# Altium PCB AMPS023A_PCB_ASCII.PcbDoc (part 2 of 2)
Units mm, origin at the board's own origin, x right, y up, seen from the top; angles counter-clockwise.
Board outline 85 x 120 mm, 4 copper layers (Top Layer, Signal Layer 1, Signal Layer 2, Bottom Layer), stack 1.567 mm thick; 131 components, 63 nets, 410 pads, 509 vias.
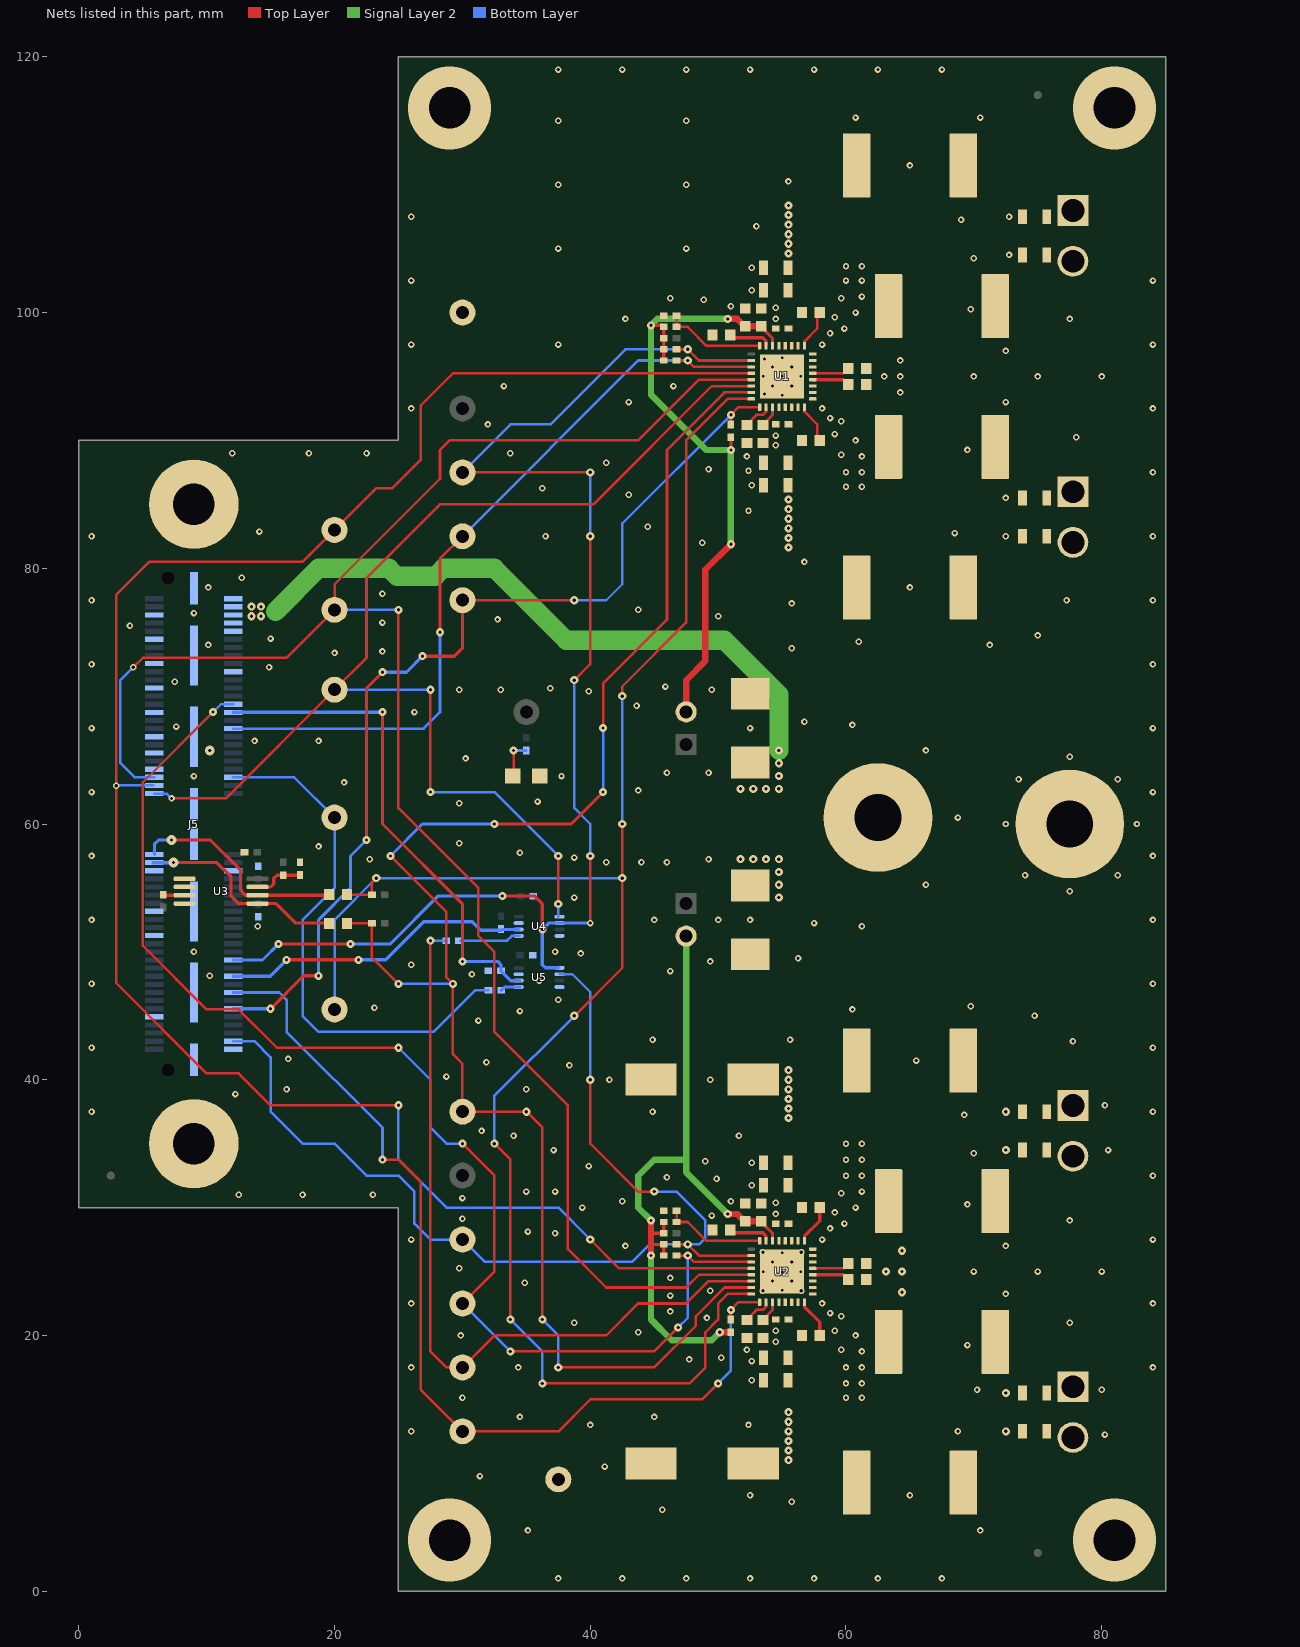
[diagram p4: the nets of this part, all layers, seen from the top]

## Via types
v1: diameter 0.508, hole 0.254, Top Layer to Bottom Layer, tented both sides, 343 vias
v2: diameter 0.635, hole 0.254, Top Layer to Bottom Layer, tented both sides, 130 vias
v3: diameter 0.508, hole 0.254, Top Layer to Bottom Layer, 14 vias
v4: diameter 0.5, hole 0.2, Top Layer to Bottom Layer, 10 vias
v5: diameter 0.762, hole 0.254, Top Layer to Bottom Layer, tented both sides, 8 vias
v6: diameter 6.5, hole 3.25, Top Layer to Bottom Layer, tented both sides, 4 vias

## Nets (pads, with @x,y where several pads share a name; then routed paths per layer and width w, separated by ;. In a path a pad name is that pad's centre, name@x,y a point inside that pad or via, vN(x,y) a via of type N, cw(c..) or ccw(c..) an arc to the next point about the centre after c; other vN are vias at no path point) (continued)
\MUTE1: J5.78 R21.1 TP14.1 U1.10 U4.2 U5.1 | length 110.7
  Top Layer w0.2: TP14.1@30,87.5 v2(40,87.5) ; v2(38.75,71.25) 40,72.5 v2(40,82.5) ; v2(40,57.5) 40,52.253 v1(40.005,52.248) ; R21.1@46.75,97.125 v2(47.625,97.125) 48.5,96.25 U1.10@52.6,96.25
  Top Layer w0.25: v2(15.625,50.625) v2(21.25,50.625) ; v2(33.125,54.375) 35.625,54.375 36.25,53.75 v2(36.25,51.744)
  Bottom Layer w0.2: TP14.1@30,87.5 33.75,91.25 36.875,91.25 42.75,97.125 v2(47.625,97.125) ; v2(38.75,71.25) 38.75,61.25 40,60 v2(40,57.5) ; v2(40,82.5) v2(40,87.5)
  Bottom Layer w0.25: J5.78@12.086,49.364 14.364,49.364 v2(15.625,50.625) ; v2(21.25,50.625) 24.375,50.625 28.125,54.375 v2(33.125,54.375)
  Bottom Layer w0.254: U5.1@37.5,48.75 36.5,48.75 36.25,49 v2(36.25,51.744) 36.756,52.25 40.003,52.25 v1(40.005,52.248)
\MUTE2: J5.98 R4.1 TP15.1 U2.10 U5.2 | length 82.7
  Top Layer w0.2: v2(40,40) 40,35 43.75,31.25 v2(45,31.25) ; R4.1@46.75,27.125 v2(47.625,27.125) 48.5,26.25 U2.10@52.6,26.25
  Bottom Layer w0.2: J5.98@12.086,43.014 13.736,43.014 15,41.75 15,37.5 17.5,35 20,35 22.5,32.5 25,32.5 26.25,31.25 26.25,28.75 27.5,27.5 TP15.1@30,27.5 31.75,25.75 43.25,25.75 44.625,27.125 v2(47.625,27.125) 48.5,27.125 49,27.625 49,29 46.75,31.25 v2(45,31.25) ; U5.2@37.6,48.25 38.6,48.25 40,46.85 v2(40,40)
\PDN1: J5.90 R23.1 TP18.1 U1.17 | length 77.4
  Top Layer w0.2: TP18.1@30,77.5 v2(38.75,77.5) ; R23.1@51,91.25 v2(51,92) 51.6,92.6 U1.17@53.25,92.6
  Top Layer w0.25: v2(15,45.554) 17.571,48.125 v2(18.75,48.125) ; v2(22.5,58.75) 22.5,70.625 v2(23.75,71.875) ; v2(26.875,73.125) 29.375,73.125 30,73.75 TP18.1@30,77.5
  Bottom Layer w0.2: J5.90@12.086,45.554 J5.90@12.086,45.57 ; v2(38.75,77.5) 41.25,77.5 42.5,78.75 42.5,83.5 v2(51,92)
  Bottom Layer w0.25: J5.90@12.086,45.554 v2(15,45.554) ; v2(18.75,48.125) 18.75,52.5 21.25,55 21.25,57.5 v2(22.5,58.75) ; v2(23.75,71.875) 25.625,71.875 v2(26.875,73.125)
\PDN2: J5.86 R6.1 TP17.1 U2.17 | length 75.5
  Top Layer w0.2: v2(23.75,33.75) 25,33.75 26.75,32 26.75,15.75 TP17.1@30,12.5 37.5,12.5 40,15 48.75,15 v2(50,16.25) ; R6.1@51,21.25 v2(51,22) 51.6,22.6 U2.17@53.25,22.6
  Bottom Layer w0.2: J5.86@12.086,46.824 15.676,46.824 16.25,46.25 16.25,43.75 23.75,36.25 v2(23.75,33.75) ; v2(50,16.25) 51,17.25 v2(51,22)
\WARN1: J5.34 R22.1 TP8.1 U1.11 | length 60.6
  Top Layer w0.2: v2(28.25,75) 28.25,80.75 TP8.1@30,82.5 ; R22.1@46.75,96.25 v2(47.625,96.25) 48.125,95.75 U1.11@52.6,95.75
  Bottom Layer w0.2: J5.34@12.086,67.461 26.961,67.461 28.25,68.75 v2(28.25,75) ; TP8.1@30,82.5 43.75,96.25 v2(47.625,96.25)
\WARN2: J5.28 R5.1 TP9.1 U2.11 | length 101.8
  Top Layer w0.2: v2(10.5,68.75) 5,63.25 5,50.5 10,45.5 12.5,45.5 15.5,42.5 v2(25,42.5) ; TP9.1@30,22.5 32.5,25 32.5,32.5 v2(30,35) ; v2(33.75,18.75) 45,18.75 v2(46.875,20.625) ; R5.1@46.75,26.25 v2(47.625,26.25) 48.125,25.75 U2.11@52.6,25.75
  Bottom Layer w0.2: v2(10.5,68.75) 11.116,69.366 J5.28@12.086,69.366 ; v2(25,42.5) 27.5,40 27.5,36.25 28.75,35 v2(30,35) ; TP9.1@30,22.5 v2(33.75,18.75) ; v2(46.875,20.625) 47.625,21.375 v2(47.625,26.25)
ADR1: R1.1 R17.1 U1.8 | length 8
  Top Layer w0.2: R1.1@46.75,99.75 R17.1@46.75,98.875 47.625,98.875 49.1,97.4 U1.8@53.25,97.4
ADR2: R2.1 R24.1 U2.8 | length 8
  Top Layer w0.2: R2.1@46.75,29.75 R24.1@46.75,28.875 47.625,28.875 49.1,27.4 U2.8@53.25,27.4
BST_A1+: C6.1 U1.1 | length 3.1
  Top Layer w0.2: U1.1@56.75,97.4 56.75,97.75 57.75,98.75 57.75,99.8 C6.1@57.95,100
BST_A1-: C9.1 U1.29 | length 3
  Top Layer w0.2: U1.29@57.4,95.25 59.8,95.25 C9.1@60.175,95.625 ; C9.1@60.237,95.562 C9.1@60.3,95.625
BST_A2+: C24.1 U2.1 | length 3.1
  Top Layer w0.25: U2.1@56.75,27.4 56.75,27.75 57.95,28.95 C24.1@57.95,30
BST_A2-: C27.1 U2.29 | length 3
  Top Layer w0.2: U2.29@57.4,25.25 59.8,25.25 C27.1@60.175,25.625 ; C27.1@60.237,25.562 C27.1@60.3,25.625
BST_B1+: C13.1 U1.24 | length 3.1
  Top Layer w0.2: U1.24@56.75,92.6 56.75,92.25 57.75,91.25 57.75,90.2 C13.1@57.95,90
BST_B1-: C10.1 U1.28 | length 3
  Top Layer w0.25: U1.28@57.4,94.75 59.8,94.75 C10.1@60.175,94.375 ; C10.1@60.237,94.438 C10.1@60.3,94.375
BST_B2+: C30.1 U2.24 | length 3.1
  Top Layer w0.25: U2.24@56.75,22.6 56.75,22.25 57.95,21.05 C30.1@57.95,20
BST_B2-: C28.1 U2.28 | length 2.9
  Top Layer w0.25: U2.28@57.4,24.75 59.8,24.75 C28.1@60.175,24.375
DVDD1: C3.2 C4.1 J2.2 R17.2 R20.2 R21.2 R22.2 R23.2 U1.6 | length 51
  Top Layer w0.25: v2(44.75,99) 45.625,99 R17.2@45.75,98.875 R20.2@45.75,98 R21.2@45.75,97.125 R22.2@45.75,96.25 ; v2(51,89.25) R23.2@51,90.25 ; C4.1@53.375,98.865 54.25,97.99 U1.6@54.25,97.4
  Top Layer w0.5: J2.2@47.5,68.77 47.5,71.25 49,72.75 49,79.875 v2(51,81.875) ; v2(50.75,99.5) 51.489,99.5 52.064,98.925 C3.2@52.125,98.925 53.315,98.925 C4.1@53.375,98.865
  Signal Layer 2 w0.5: v2(50.75,99.5) 45.25,99.5 v2(44.75,99) 44.75,93.567 49.067,89.25 v2(51,89.25) v2(51,81.875)
DVDD2: C21.2 C22.1 J3.2 R3.2 R4.2 R5.2 R6.2 R24.2 U2.6 | length 54.7
  Top Layer w0.25: 44.75,27.125 R4.2@45.75,27.125 R5.2@45.75,26.25 ; 44.75,28 R3.2@45.75,28 R24.2@45.75,28.875 ; C22.1@53.375,28.865 54.25,27.99 U2.6@54.25,27.4
  Top Layer w0.5: v2(44.75,26.25) 44.75,27.125 44.75,28 v2(44.75,29) ; v2(50.125,20.25) R6.2@51,20.25 ; v2(50.75,29.5) 51.489,29.5 52.064,28.925 C21.2@52.125,28.925 53.315,28.925 C22.1@53.375,28.865
  Signal Layer 2 w0.5: v2(44.75,26.25) 44.75,21.25 46.375,19.625 49.5,19.625 v2(50.125,20.25) ; v2(44.75,29) 43.75,30 43.75,32.5 45,33.75 47.5,33.75 ; J3.2@47.5,51.23 47.5,33.75 ; v2(50.75,29.5) 47.5,32.75 47.5,33.75
GND: C1.2 C2.1 C3.1 C4.2 C5.2 C7.2 C8.1 C11.1 C12.1 C14.2 C15.2 C16.2 C17.1 C18.2 C19.2 C20.1 C21.1 C22.2 C23.2 C25.2 C26.2 C29.2 C31.2 C32.2 C33.2 C34.2 C35.2 C36.1 C37.1 C38.1 C39.1 C40.1 C41.2 C42.2 C43.2 C44.2 C45.1 D1.2 J5.5 J5.10 J5.11 J5.17 J5.20 J5.23 J5.29 J5.35 J5.39 J5.43 J5.55 J5.56 J5.65 J5.71 J5.91 J5.100 J5.101 J5.102 J5.103 J5.104 J5.105 J5.106 J5.107 J5.108 J7.1 pad.0 R1.2 R2.2 R10.1 R16.2 TP2.1 TP3.1 U1.5 U1.20 U1.25 U1.26 U1.31 U1.32 U1.33 U2.5 U2.20 U2.25 U2.26 U2.31 U2.32 U2.33 U3.1 U3.2 U3.4 U4.4 U4.7 U5.4 U5.7
  other v1: 37.5,1 42.5,1 47.5,1 52.5,1 57.5,1 62.5,1 67.5,1 35.125,4.75 70.5,4.75 45.625,6.375 55.75,7 52.5,7.5 65,7.5 31.375,9 41.125,9.75 80.25,12.25 26,12.5 68.75,12.5 40,13 52.375,13 34.5,13.625 45,13.625 30,15.125 60,15.125 61.25,15.125 70.25,15.75 80,15.75 60,16.25 61.25,16.25 52.625,16.5 26,17.5 34.375,17.5 60,17.5 61.25,17.5 84,17.5 52.625,18 47.75,18.125 50.25,18.25 61.25,18.75 52.25,18.875 59.625,18.875 69.5,19.25 54.5,19.5 29.875,20 60.75,20 43.75,20.25 54.5,20.375 59.125,20.375 38.75,21 77.5,21 49.125,21.375 59.625,21.5 58.75,21.75 46.25,21.875 26,22.5 58.125,22.5 84,22.5 46.25,23.125 72.5,23.25 49.375,23.5 34.875,24.125 46.25,24.5 70,25 75,25 80,25 29.75,25.25 42.75,27 72.5,27 26,27.5 58.125,27.5 84,27.5 37.25,28 35.125,28.125 58.75,28.375 59.875,28.75 77.5,29 30,29.125 49.5,29.375 54.5,29.5 59.125,29.625 39.375,30 60.75,30 69.5,30.25 54.5,30.375 42.5,30.5 51,30.5 30,30.75 12.5,31 17.5,31 23,31 59.625,31.125 35,31.25 37.25,31.25 61.25,31.25 52.625,31.75 49.875,32.25 46,32.375 60,32.5 61.25,32.5 84,32.5 39.875,33.25 52.625,33.5 49,33.625 60,33.75 61.25,33.75 70,34.25 37.125,34.5 80.5,34.5 60,35 61.25,35 34,35.625 51.625,35.625 31.5,36 69.25,37.25 1,37.5 44.875,37.5 84,37.5 80.25,38 12.25,38.875 16.25,39.25 35,39.25 41.5,40 49.375,40 28.75,40.25 38.375,41.125 31.875,41.375 65.5,41.5 16.375,41.625 1,42.5 84,42.5 77.75,43 44.875,43.125 55.625,43.125 31.25,44.625 74.75,45 34.5,45.375 60.5,45.5 23.125,45.625 69.75,45.75 37.5,46.25 1,47.5 84,47.5 36,47.75 10.25,48.125 30.75,48.25 46.25,48.5 26,49 49.375,49.25 56.25,49.5 39.25,49.875 9,50 37.25,50 14,52 61.25,52 57.5,52.25 1,52.5 45,52.5 50,52.5 52.5,52.5 84,52.5 38.75,54.25 77.5,54.75 66.25,55.25 74,56 81.25,56 41.25,57 44,57 46,57 22.75,57.25 49.25,57.25 38.75,57.375 1,57.5 84,57.5 34.5,57.75 18.75,58.25 29.75,58.5 72.5,60 82.75,60 68.75,60.5 29.75,61.625 35.875,61.75 1,62.5 84,62.5 43.75,62.625 20.75,63.25 73.5,63.5 81.25,63.5 9,63.75 37.75,63.75 46,64 49.25,64 30.25,65.125 77.5,65.25 66.25,65.75 13.75,66.5 18.75,66.5 1,67.5 52.5,67.5 84,67.5 7.625,67.625 60.5,67.75 56.75,68 26.25,68.75 43.625,69.25 39.875,70.375 29.75,70.5 33,70.5 49.5,70.5 36.875,70.625 45.875,70.75 7.5,71.125 14.875,72.25 1,72.5 84,72.5 20,73.375 23.75,73.5 55.75,73.75 10.125,74 71.25,74 61,74.25 15,74.5 75,74.75 4,75.5 23.75,75.75 32.75,76 50,76.25 9,76.5 43.75,76.75 55.75,77.25 1,77.5 77.25,77.5 84,77.5 23.75,78 10.125,78.5 65,78.5 12.75,79.25 56.75,80.5 48.75,82 1,82.5 36.5,82.5 72.5,82.5 84,82.5 68.5,82.75 14.125,82.875 44.5,83.25 52.375,84.5 72.5,85.5 43,85.75 36.25,86.25 60,86.375 61.25,86.375 52.625,86.5 60,87.5 61.25,87.5 84,87.5 52.375,87.625 49.25,87.75 41.25,88.25 52.25,88.75 61.25,88.75 59.625,88.875 12,89 18,89 22.5,89 33.75,89 69.5,89.25 54.5,89.625 60.75,90 78,90.25 54.5,90.375 59.125,90.5 32,91.25 59.625,91.5 58.75,91.75 26,92.5 58.125,92.5 84,92.5 43,93 72.5,93 64.25,93.75 33.25,94.25 46.5,94.25 63,95 64.25,95 70,95 75,95 80,95 64.25,96.25 72.5,97 26,97.5 37.5,97.5 58.125,97.5 84,97.5 58.75,98.375 59.875,98.75 42.75,99.5 54.5,99.5 77.5,99.5 59.125,99.625 60.75,100 69.75,100.25 54.5,100.375 51,100.5 48.875,101 46.25,101.125 59.625,101.125 61.25,101.25 52.625,101.75 26,102.5 60,102.5 61.25,102.5 84,102.5 52.625,103.5 60,103.625 61.25,103.625 70,104.25 72.75,104.5 37.5,105 47.5,105 53,106.75 69,107.25 26,107.5 72.75,107.5 37.5,110 47.5,110 55.5,110.25 65,111.5 37.5,115 47.5,115 60.75,115.25 70.5,115.25 37.5,119 42.5,119 47.5,119 52.5,119 57.5,119 62.5,119 67.5,119
  other v2: 72.5,12.5 72.5,15.5 64.375,23.375 63.125,25 64.375,25 64.375,26.625 72.5,34.5 72.5,37.5
  other v3: 53.5,23.5 56.5,23.5 54.25,24.25 55.75,24.25 54.25,25.75 55.75,25.75 53.5,26.5 56.5,26.5 53.625,93.625 54.25,94.25 55.75,94.25 54.25,95.75 55.75,95.75 53.625,96.375
  other v4: 55,23.525 53.525,25 55,25 56.475,25 55,26.475 55,93.525 53.525,95 55,95 56.475,95 55,96.475
  other v5: 10.25,65.75
  other v6: 29,4 81,4 29,116 81,116
LRCLK: J5.47 TP11.1 U1.12 U2.12 | length 154
  Top Layer w0.2: v2(25,38) 15,38 12.5,40.5 10,40.5 2.914,47.586 2.914,77.914 5.5,80.5 17.5,80.5 TP11.1@20,83 23.25,86.25 24.5,86.25 26.75,88.5 26.75,92.75 29.25,95.25 U1.12@52.6,95.25 ; v2(40,27.5) 42.25,25.25 U2.12@52.6,25.25
  Bottom Layer w0.2: v1(2.921,62.991) 2.946,63.016 J5.47@5.812,63.016 ; v2(25,38) 25,33.75 28.75,30 37.5,30 v2(40,27.5)
NetC5_1: C5.1 U1.7 | length 3.4
  Top Layer w0.254: C5.1@50.95,98.25 51.173,98.027 53.481,98.027 53.75,97.758 U1.7@53.75,97.4
NetC14_1: C14.1 U1.18 | length 2.3
  Top Layer w0.2: C14.1@52.25,91.2 52.25,91.25 53,92 53.5,92 53.75,92.25 U1.18@53.75,92.6
NetC15_1: C15.1 U1.19 | length 1.7
  Top Layer w0.2: C15.1@53.5,91.2 53.5,91.25 54.25,92 U1.19@54.25,92.6
NetC23_1: C23.1 U2.7 | length 3.4
  Top Layer w0.254: C23.1@50.95,28.25 51.173,28.027 53.481,28.027 53.75,27.758 U2.7@53.75,27.4
NetC32_1: C32.1 U2.18 | length 2.3
  Top Layer w0.2: C32.1@52.25,21.2 52.25,21.25 53,22 53.5,22 53.75,22.25 U2.18@53.75,22.6
NetC33_1: C33.1 U2.19 | length 1.7
  Top Layer w0.2: C33.1@53.5,21.2 53.5,21.25 54.25,22 U2.19@54.25,22.6
NetD1_1: D1.1 R7.1 | length 3
  Top Layer w0.2: D1.1@33.95,63.75 34,63.8 v2(34,65.75)
  Bottom Layer w0.2: v2(34,65.75) R7.1@35,65.75
NetR8_1: R8.1 U3.3 | length 1.7
  Top Layer w0.254: R8.1@6.604,54.474 6.653,54.425 U3.3@8.275,54.425
NetR9_2: R9.2 R10.2 U3.7 | length 4
  Top Layer w0.254: U3.7@13.975,55.075 15,55.075 15.25,55.325 15.25,55.75 15.5,56 R9.2@16,56 17.283,56 R10.2@17.297,56.014
NetR15_1: R15.1 U5.5 | length 2.6
  Bottom Layer w0.254: R15.1@33.037,46.99 33.297,47.25 33.372,47.25 ; U5.5@34.4,47.25 33.372,47.25 ; U5.5@34.5,47.25 33.372,47.25
NetR18_1: R18.1 U4.5 | length 4.8
  Bottom Layer w0.2: R18.1@29.835,50.876 33.5,50.876 33.874,51.25 U4.5@34.5,51.25
OUT1+: C41.1 J8.1 L1.2
OUT1-: C42.1 J8.2 L2.2
OUT2+: C43.1 J9.2 L3.2
OUT2-: C44.1 J9.1 L4.2
OUT3+: C25.1 J11.1 L5.2
OUT3-: C26.1 J11.2 L6.2
OUT4+: C29.1 J4.2 L7.2
OUT4-: C31.1 J4.1 L8.2
OUT_A1+: C6.2 L1.1 U1.2
OUT_A1-: C9.2 L2.1 U1.30
OUT_A2+: C24.2 L5.1 U2.2
OUT_A2-: C27.2 L6.1 U2.30
OUT_B1+: C13.2 L3.1 U1.23
OUT_B1-: C10.2 L4.1 U1.27
OUT_B2+: C30.2 L7.1 U2.23
OUT_B2-: C28.2 L8.1 U2.27
PVDD: J1.2 J5.2 J5.4 J5.6 J5.8 J6.1 J10.2 | length 49.8
  Signal Layer 2 w1.5: 15.375,76.625 18.75,80 24.25,80 24.875,79.375 27.875,79.375 28.5,80 32.5,80 38.125,74.375 50.5,74.375 54.75,70.125 v2(54.75,65.75)
  other v2: 54.75,54.25 54.75,55.25 54.75,56.25 51.75,57.25 52.75,57.25 53.75,57.25 54.75,57.25 51.75,62.75 52.75,62.75 53.75,62.75 54.75,62.75 54.75,63.75 54.75,64.75 13.5,76.25 14.25,76.25 13.5,77 14.25,77
PVDD1: C1.1 C2.2 C16.1 C17.2 C37.2 C38.2 J10.1 U1.3 U1.4 U1.21 U1.22
  other v2: 55.5,81.625 55.5,82.375 55.5,83.125 55.5,83.875 55.5,84.625 55.5,85.375 55.5,104.625 55.5,105.375 55.5,106.125 55.5,106.875 55.5,107.625 55.5,108.375
PVDD2: C18.1 C19.1 C20.2 C34.1 C35.1 C36.2 C39.2 C40.2 J1.1 U2.3 U2.4 U2.21 U2.22
  other v2: 55.5,10.25 55.5,11 55.5,11.75 55.5,12.5 55.5,13.25 55.5,14 55.5,37 55.5,37.75 55.5,38.5 55.5,39.25 55.5,40 55.5,40.75
SCL: R11.1 R13.1 TP6.1 U1.16 U2.16 | length 143.8
  Top Layer w0.2: R13.1@20.979,54.482 22.826,54.482 R11.1@22.926,54.582 ; R11.1@22.926,54.482 R11.1@22.926,54.582 ; v2(23.264,55.764) 22.926,55.426 R11.1@22.926,54.582 ; v2(32.5,35) 33.75,33.75 v2(33.75,21.25) ; v2(36.25,16.25) 47.75,16.25 49,17.5 49,20.25 50,21.25 50,22.5 50.75,23.25 U2.16@52.6,23.25 ; v2(38.75,45) 42.5,48.75 v2(42.5,55.764) v2(42.5,60) ; v2(42.5,70) 42.5,70.75 47.5,75.75 47.5,90 50.75,93.25 U1.16@52.6,93.25
  Bottom Layer w0.2: TP6.1@20,45.5 20,52.5 v2(23.264,55.764) v2(42.5,55.764) ; v2(32.5,35) 32.5,38.75 v2(38.75,45) ; v2(33.75,21.25) 36.25,18.75 v2(36.25,16.25) ; v2(42.5,60) v2(42.5,70)
SCL-PPCMB_OUT: J5.51 R13.2 U3.6 | length 18.4
  Top Layer w0.25: v5(7.25,58.75) 10.279,58.75 12.649,56.38 12.649,54.805 ; 13.024,54.43 U3.6@14.124,54.43
  Top Layer w0.254: 12.649,54.805 13.024,54.43 13.029,54.425 U3.6@13.975,54.425 19.522,54.425 R13.2@19.579,54.482
  Bottom Layer w0.254: J5.51@5.914,57.619 5.914,58.414 6.25,58.75 v5(7.25,58.75)
SCLK: J5.45 TP12.1 U1.13 U2.13 | length 147.7
  Top Layer w0.2: v1(4.25,72.25) 5,73 16.25,73 TP12.1@20,76.75 20,78.75 28.25,87 28.25,89.25 29,90 43.75,90 48.5,94.75 U1.13@52.6,94.75 ; v2(25,76.75) 25,61.25 31.25,55 31.25,51.25 32.5,50 32.5,43.75 38.25,38 38.25,26.75 41.25,23.75 47.5,23.75 48.5,24.75 U2.13@52.6,24.75
  Bottom Layer w0.2: v1(4.25,72.25) 3.253,71.253 3.253,64.766 4.352,63.667 J5.45@5.917,63.667 ; TP12.1@20,76.75 v2(25,76.75)
SDA: R12.1 R14.1 TP7.1 U1.15 U2.15 | length 134.3
  Top Layer w0.2: R14.1@20.979,52.232 R12.1@22.926,52.232 22.926,49.574 v2(25,47.5) ; v2(24.375,57.5) 28.75,53.125 28.75,48 v2(29.25,47.5) 29.25,42 30,41.25 TP7.1@30,37.5 v2(35,37.5) 36.25,36.25 v2(36.25,21.25) ; v2(37.5,17.5) 45,17.5 48.25,20.75 48.25,21.5 50.5,23.75 U2.15@52.6,23.75 ; v2(41,67.5) 41,71 46,76 46,89.25 50.5,93.75 U1.15@52.6,93.75
  Top Layer w0.25: v2(32.5,60) 38.5,60 v2(41,62.5)
  Bottom Layer w0.2: v2(25,47.5) v2(29.25,47.5) ; v2(36.25,21.25) 37.5,20 v2(37.5,17.5) ; v2(41,62.5) v2(41,67.5)
  Bottom Layer w0.25: v2(24.375,57.5) 26.875,60 v2(32.5,60)
SDA-PPCMB_OUT: J5.53 R14.2 U3.5 | length 16.5
  Top Layer w0.25: v5(7.414,56.984) 10.789,56.984 11.914,55.859 11.914,54.359
  Top Layer w0.254: 11.914,54.359 12.498,53.775 U3.5@13.975,53.775 15.425,53.775 16.95,52.25 19.461,52.25 R14.2@19.479,52.232
  Bottom Layer w0.25: J5.53@5.828,56.967 v5@7.398,56.967
SDIN1: J5.49 TP10.1 U1.14 U4.1 | length 96.2
  Top Layer w0.2: v1(7.25,62) 11.5,62 TP10.1@20,70.5 22.5,73 22.5,79.25 28.25,85 40.25,85 49.5,94.25 U1.14@52.6,94.25 ; v2(27.5,62.5) v2(27.5,70.5) ; v2(37.5,53.75) v2(37.5,57.5)
  Bottom Layer w0.2: J5.49@5.914,62.381 6.869,62.381 v1(7.25,62) ; TP10.1@20,70.5 v2(27.5,70.5) ; v2(27.5,62.5) 32.5,62.5 v2(37.5,57.5) ; U4.1@37.5,52.75 v2(37.5,53.75)
SDIN2: R18.2 TP16.1 U2.14 | length 61.8
  Top Layer w0.2: v2(27.501,50.876) v2(27.501,50.876) 27.5,18.75 28.75,17.5 TP16.1@30,17.5 32.5,20 41.25,20 43.75,22.5 47.5,22.5 49.25,24.25 U2.14@52.6,24.25
  Bottom Layer w0.2: v2(27.501,50.876) v2(27.501,50.876) R18.2@28.735,50.876
SDIN-SEL: J5.82 R19.2 U4.6 | length 24.3
  Top Layer w0.254: v2(16.25,49.375) v2(21.875,49.375)
  Bottom Layer w0.254: J5.82@12.086,48.094 14.969,48.094 v2(16.25,49.375) ; v2(21.875,49.375) 24,49.375 26.974,52.349 30.785,52.349 31.452,51.683 R19.2@33.02,51.683 ; R19.2@33.087,51.75 U4.6@34.4,51.75
SDOUT: J5.46 R15.2 TP13.1 | length 44.4
  Bottom Layer w0.2: J5.46@12.058,63.667 14.321,63.667 ; J5.46@12.086,63.651 16.849,63.651 TP13.1@20,60.5 20,55 17.5,52.5 17.5,45 18.75,43.75 27.75,43.75 30.99,46.99 R15.2@32.037,46.99
SDOUT-SEL: J5.30 R16.1 U5.6 | length 39.2
  Top Layer w0.254: v2(23.75,68.75) 23.75,60 30,53.75 v2(30,49.25)
  Bottom Layer w0.254: J5.30@12.086,68.731 23.731,68.731 v2(23.75,68.75) ; v2(30,49.25) 32.75,49.25 33.012,48.988 R16.1@33.012,48.514 33.776,47.75 U5.6@34.5,47.75
pads on no net: FID1.1 FID2.1 FID3.1 FID4.1 FID5.1 FID6.1 J5.1 J5.3 J5.7 J5.9 J5.12 J5.13 J5.14 J5.15 J5.16 J5.18 J5.19 J5.21 J5.25 J5.26 J5.27 J5.31 J5.32 J5.33 J5.36 J5.37 J5.38 J5.40 J5.41 J5.42 J5.44 J5.48 J5.50 J5.52 J5.54 J5.57 J5.59 J5.61 J5.63 J5.66 J5.67 J5.68 J5.69 J5.70 J5.72 J5.73 J5.74 J5.75 J5.76 J5.77 J5.79 J5.80 J5.81 J5.83 J5.84 J5.85 J5.87 J5.88 J5.89 J5.92 J5.93 J5.94 J5.95 J5.96 J5.97 J5.99 J5.MH1 J5.MH2 SH-J1.0 SH-J2.0 U1. U2. U4.3 U5.3

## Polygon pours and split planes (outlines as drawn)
GND on Top Layer "GND Top Copper" (solid, remove dead copper, pour order 200): 25.5,118 27,119.5 83,119.5 84.5,118 84.5,1.5 83.5,0.5 27,0.5 25.5,2 25.5,30.5 7.5,30.5 0.5,37.5 0.5,82.5 7.5,89.5 25.5,89.5
+3.3V on Top Layer "3.3V Top Copper" (solid, remove dead copper, pour order 186): 9.375,55.5 9.875,56 11,56 11.5,55.5 11.5,54 11,53.5 9.875,53.5 9.375,54 9.375,55.5
PVDD on Top Layer "PVDD Top Copper" (solid, pour order 189): 51,66.25 51,53.75 62,53.75 67,58.75 67,62.25 63,66.25
PVDD2 on Top Layer "PVDD2 Top Copper" (solid, pour order 197): 55.1,22.85 55.15,22.9 55.85,22.9 55.9,22.85 55.9,9.9 54.75,8.75 50.75,8.75 50.75,11.25 53,11.25 54.25,12.5 54.25,18.5 55.1,19.35
OUT4- on Top Layer "OUT4- Top Copper" (solid, pour order 176): 70.5,22 70.5,17 74.75,17 75.25,16.5 75.25,14.75 79,14.75 79,17.25 74.25,22
OUT_B2- on Top Layer "OUT_B2- Top Copper" (solid, pour order 183): 57.15,24.375 58.875,24.375 59.5,23.75 61,23.75 61.125,23.875 61.125,24.875 62,24.875 64.5,22.375 64.5,17 62.25,17 62.25,19.625 57.75,24.125 57.15,24.125
OUT_B2+ on Top Layer "OUT_B2+ Top Copper" (solid, pour order 185): 56.125,22.875 56.125,12.375 57.5,11 57.5,8.25 59.75,6 62,6 62,11 59,14 59,17.75 57.25,19.5 57.25,21.25 56.375,22.125 56.375,22.875 56.35,22.9 56.15,22.9
PVDD2 on Top Layer "PVDD2 Top Copper" (solid, pour order 198): 55.1,27.15 55.15,27.1 55.85,27.1 55.9,27.15 55.9,40.85 54.25,42.5 54.25,51 54,51.25 51,51.25 50.75,51 50.75,38.75 54.25,35.25 54.25,31.5 55.1,30.65
OUT4+ on Top Layer "OUT4+ Top Copper" (solid, pour order 177): 68,6 68,11 74.75,11 75.25,11.5 75.25,13.25 79,13.25 79,10.75 74.25,6
OUT3+ on Top Layer "OUT3+ Top Copper" (solid, pour order 174): 68,44 68,39 74.75,39 75.25,38.5 75.25,36.75 79,36.75 79,39.25 74.25,44
OUT_A2+ on Top Layer "OUT-A2 Top Copper" (solid, pour order 179): 56.125,27.125 56.125,37.625 57.5,39 57.5,41.75 59.75,44 62,44 62,39 59,36 59,32.25 57.25,30.5 57.25,28.75 56.375,27.875 56.375,27.125 56.35,27.1 56.15,27.1
OUT_A2- on Top Layer "OUT-B2 Top Copper" (solid, pour order 181): 57.15,25.625 58.875,25.625 59.5,26.25 61,26.25 61.125,26.125 61.125,25.125 62,25.125 64.5,27.625 64.5,33 62.25,33 62.25,30.375 57.75,25.875 57.15,25.875
OUT3- on Top Layer "OUT3- Top Copper" (solid, pour order 175): 70.5,28 70.5,33 74.75,33 75.25,33.5 75.25,35.25 79,35.25 79,32.75 74.25,28
OUT1- on Top Layer "OUT1- Top Copper" (solid, pour order 171): 70.5,98 70.5,103 74.75,103 75.25,103.5 75.25,105.25 79,105.25 79,102.75 74.25,98
OUT_A1- on Top Layer "OUT_A1- Top Copper" (solid, pour order 180): 57.15,95.625 58.875,95.625 59.5,96.25 61,96.25 61.125,96.125 61.125,95.125 62,95.125 64.5,97.625 64.5,103 62.25,103 62.25,100.375 57.75,95.875 57.15,95.875
OUT1+ on Top Layer "OUT1+ Top Copper" (solid, pour order 170): 68,114 68,109 74.75,109 75.25,108.5 75.25,106.75 79,106.75 79,109.25 74.25,114
OUT2+ on Top Layer "OUT2+ Top Copper" (solid, pour order 173): 68,76 68,81 74.75,81 75.25,81.5 75.25,83.25 79,83.25 79,80.75 74.25,76
OUT_B1+ on Top Layer "OUT_B1+ Top Copper" (solid, pour order 184): 56.125,92.875 56.125,82.375 57.5,81 57.5,78.25 59.75,76 62,76 62,81 59,84 59,87.75 57.25,89.5 57.25,91.25 56.375,92.125 56.375,92.875 56.35,92.9 56.15,92.9
OUT_B1- on Top Layer "OUT_B1- Top Copper" (solid, pour order 182): 57.15,94.375 58.875,94.375 59.5,93.75 61,93.75 61.125,93.875 61.125,94.875 62,94.875 64.5,92.375 64.5,87 62.25,87 62.25,89.625 57.75,94.125 57.15,94.125
OUT2- on Top Layer "OUT2- Top Copper" (solid, pour order 172): 70.5,92 70.5,87 74.75,87 75.25,86.5 75.25,84.75 79,84.75 79,87.25 74.25,92
OUT_A1+ on Top Layer "OUT_A1+ Top Copper" (solid, pour order 178): 56.125,97.125 56.125,107.625 57.5,109 57.5,111.75 59.75,114 62,114 62,109 59,106 59,102.25 57.25,100.5 57.25,98.75 56.375,97.875 56.375,97.125 56.35,97.1 56.15,97.1
PVDD1 on Top Layer "PVDD1 Top Copper" (solid, pour order 195): 55.1,92.85 55.15,92.9 55.85,92.9 55.9,92.85 55.9,79.9 54.25,78.25 54.25,69 54,68.75 51,68.75 50.75,69 50.75,79 54.25,82.5 54.25,88.5 55.1,89.35
PVDD1 on Top Layer "PVDD1 Top Copper" (solid, pour order 194): 55.1,97.15 55.15,97.1 55.85,97.1 55.9,97.15 55.9,108.5 55.75,108.75 54.5,108.75 54.25,108.5 54.25,107.5 54.25,101.5 55.1,100.65
GND on Bottom Layer "GND Bottom Copper" (solid, remove dead copper, pour order 203): 25.5,117.5 27.5,119.5 82.5,119.5 84.5,117.5 84.5,2.5 82.5,0.5 27.5,0.5 25.5,2.5 25.5,30.5 7.5,30.5 0.5,37.5 0.5,82.5 7.5,89.5 25.5,89.5
+3.3V on Bottom Layer "3.3V Bottom Copper" (solid, remove dead copper, pour order 188): 12.961,55.964 10.079,55.964 9.579,55.464 9.579,53.964 10.079,53.464 12.961,53.464 14.478,53.464 14.478,54.736 14.478,55.964
PVDD on Bottom Layer "PVDD Bottom Copper" (solid, remove dead copper, pour order 192): 11.25,77.875 14.125,77.875 14.625,77.375 14.625,75.875 14.25,75.5 11.25,75.5
PVDD on Bottom Layer "PVDD Bottom Copper" (solid, pour order 193): 51.25,63 51.25,57.25 51.75,56.75 53.75,56.75 54.25,56.25 54.25,54 54.5,53.75 62,53.75 67,58.75 67,62.25 63,66.25 54.5,66.25 54,65.75 54,63.5 53.75,63.25 51.5,63.25
PVDD2 on Signal Layer 2 "PVDD2 Copper Layer 3" (solid, remove dead copper, pour order 199): 55.5,41.25 62.5,41.25 68.75,35 68.75,15 63.5,9.75 55.5,9.75 55,10.25 55,14 55.5,14.5 62,14.5 65,17.5 65,32.5 61,36.5 55.5,36.5 55,37 55,40.75
PVDD1 on Signal Layer 2 "PVDD1 Copper Layer 3" (solid, remove dead copper, pour order 196): 55.25,108.75 65,108.75 68.75,105 68.75,85 65,81.25 55.25,81.25 55,81.5 55,85.5 55.25,85.75 63.25,85.75 65,87.5 65,102.5 63.25,104.25 55.25,104.25 55,104.5 55,108.5
PVDD on Signal Layer 2 "PVDD Copper Layer 3" (solid, pour order 191): 51,66.25 51,53.75 62,53.75 67,58.75 67,62.25 63,66.25
PVDD on Signal Layer 2 "PVDD Copper Layer 3" (solid, remove dead copper, pour order 190): 11.25,77.875 14.125,77.875 14.625,77.375 15.375,77.375 15.375,75.875 14.625,75.875 14.25,75.5 11.25,75.5
GND on Signal Layer 2 "GND  Copper Layer 3" (solid, remove dead copper, pour order 202): 25.5,117.5 27.5,119.5 82.5,119.5 84.5,117.5 84.5,2.5 82.5,0.5 27.5,0.5 25.5,2.5 25.5,30.5 7.5,30.5 0.5,37.5 0.5,82.5 7.5,89.5 25.5,89.5
+3.3V on Signal Layer 2 "3.3V Copper Layer 3" (solid, remove dead copper, pour order 187): 9.375,55.5 9.875,56 11,56 11.5,55.5 11.5,54 11,53.5 9.875,53.5 9.375,54 9.375,55.5
GND on Signal Layer 1 "GND Copper Layer 2" (solid, remove dead copper, pour order 201): 25.5,117.5 27.5,119.5 82.5,119.5 84.5,117.5 84.5,2.5 82.5,0.5 27.5,0.5 25.5,2.5 25.5,30.5 7.5,30.5 0.5,37.5 0.5,82.5 7.5,89.5 25.5,89.5

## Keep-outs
Keep-Out Layer:
  lines w0.254: -0.25,29.75 24.75,29.75 24.75,-0.25 85.25,-0.25 85.25,120.25 24.75,120.25 24.75,90.25 -0.25,90.25 -0.25,29.75

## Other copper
Top Layer:
  text ".Layer_Name" at 14.656,-21.806 h1.52
Signal Layer 1:
  text ".Layer_Name" at 14.656,-21.806 h1.52
Signal Layer 2:
  text ".Layer_Name" at 14.656,-21.806 h1.52
Bottom Layer:
  text ".Layer_Name" at 14.656,-21.806 h1.52

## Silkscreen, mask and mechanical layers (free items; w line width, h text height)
Top Overlay:
  lines w0.25: 59.85,5.625 59.85,3.35 70.15,3.35 70.15,5.625 ; 59.85,11.375 59.85,13.65 70.15,13.65 70.15,11.375 ; 59.85,38.625 59.85,36.35 70.15,36.35 70.15,38.625 ; 59.85,44.375 59.85,46.65 70.15,46.65 70.15,44.375 ; 59.85,75.625 59.85,73.35 70.15,73.35 70.15,75.625 ; 59.85,81.375 59.85,83.65 70.15,83.65 70.15,81.375 ; 59.85,108.625 59.85,106.35 70.15,106.35 70.15,108.625 ; 59.85,114.375 59.85,116.65 70.15,116.65 70.15,114.375 ; 62.35,16.625 62.35,14.35 72.65,14.35 72.65,16.625 ; 62.35,22.375 62.35,24.65 72.65,24.65 72.65,22.375 ; 62.35,27.625 62.35,25.35 72.65,25.35 72.65,27.625 ; 62.35,33.375 62.35,35.65 72.65,35.65 72.65,33.375 ; 62.35,86.625 62.35,84.35 72.65,84.35 72.65,86.625 ; 62.35,92.375 62.35,94.65 72.65,94.65 72.65,92.375 ; 62.35,97.625 62.35,95.35 72.65,95.35 72.65,97.625 ; 62.35,103.375 62.35,105.65 72.65,105.65 72.65,103.375
  text "+" at 80,109.375 h1.5
  text "-" at 79.75,102.25 h1.25
  text "-" at 80,87.375 h1.5
  text "+" at 80,79.875 h1.25
  text "PVDD RANGE" at 57,50.625 h1.5
  text "4.5V - 26.4V" at 57.5,48.625 h1.25
  text "+" at 80,39.375 h1.5
  text "-" at 79.75,32.25 h1.25
  text "-" at 80,17.375 h1.5
  text "+" at 80,9.875 h1.25
  text "AMPS023A" at 58.125,0.875 h1.5
  text "TAS5825MEVM" at 35.375,0.75 h2
  text ".Layer_Name" at 14.656,-21.806 h1.52
Bottom Overlay:
  text ".Layer_Name" at 14.656,-21.806 h1.52
Top Paste:
  text ".Layer_Name" at 14.656,-21.806 h1.52
Bottom Paste:
  text ".Layer_Name" at 14.656,-21.806 h1.52
Top Solder:
  text ".Layer_Name" at 14.656,-21.806 h1.52
Bottom Solder:
  text ".Layer_Name" at 14.656,-21.806 h1.52
Drill Guide:
  text ".Layer_Name" at 95.25,29.25 h1.52
M1 Board Outline:
  the board outline again, w0.254
  text ".Layer_Name" at 56.75,-21.875 h1.52
M2 Board Dimensions:
  text ".Layer_Name" at 82.5,-22 h1.52
M3 3D STEP Top:
  text ".Layer_Name" at 14.656,-21.806 h1.52
M4 3D STEP Bottom:
  text ".Layer_Name" at 14.656,-21.806 h1.52
M5 Assembly Top:
  lines w0.254: -7.417,-23.626 160.223,-23.626 ; -7.417,-18.462 160.274,-18.462 ; -7.417,-13.297 -7.417,-28.791 94.31,-28.791 160.274,-28.791 160.274,-13.297 -7.404,-13.297 -7.404,-28.791 32.614,-28.791 ; 55.194,-28.791 55.194,-13.297 ; 87.376,-18.462 87.376,-13.297 ; 108.712,-18.462 108.712,-13.297 ; 124.511,-28.956 124.511,-23.804
  text "COMPONENTS MARKED 'DNP' SHOULD NOT BE POPULATED." at 29.299,-8.09 h1.52
  text "ASSEMBLY VARIANT:" at 29.286,-11.024 h1.52
  text ".VariantName" at 55.601,-11.024 h1.52
  text "PCB VIEWED FROM TOP SIDE" at -5.804,-16.654 h1.52
  text "BOARD #:" at 57.099,-16.654 h1.52
  text ".PRJ_Number" at 70.955,-16.654 h1.52
  text "REV:" at 92.405,-16.654 h1.52
  text ".PCB_Rev" at 99.809,-16.654 h1.52
  text "SVN REV:" at 113.69,-16.654 h1.52
  text ".VersionControl_RevNumber" at 126.543,-16.654 h1.52
  text "PLOT NAME =" at -5.804,-27.034 h1.52
  text ".plot_File_Name" at 14.656,-27.034 h1.52
  text "GENERATED    :" at 57.15,-27.034 h1.52
  text ".Print_Date" at 79.235,-27.034 h1.52
  text ".Print_Time" at 97.752,-27.034 h1.52
  text "TEXAS INSTRUMENTS" at 129.87,-27.034 h1.52
M6 Assembly Bottom:
  lines w0.254: -7.429,-18.474 160.261,-18.474 ; -7.379,-23.639 160.261,-23.639 ; 28.334,-28.969 28.334,-23.817 ; 44.133,-18.474 44.133,-13.31 ; 65.468,-18.474 65.468,-13.31 ; 97.65,-28.804 97.65,-13.31 ; 120.231,-28.804 160.249,-28.804 160.249,-13.31 -7.429,-13.31 -7.429,-28.804 58.534,-28.804 160.261,-28.804 160.261,-13.31
  text "COMPONENTS MARKED 'DNP' SHOULD NOT BE POPULATED." at 154.991,-8.077 h1.52
  text ".VariantName" at 128.473,-11.024 h1.52
  text "ASSEMBLY VARIANT:" at 154.864,-11.024 h1.52
  text ".VersionControl_RevNumber" at 26.302,-16.667 h1.52
  text "SVN REV:" at 39.154,-16.667 h1.52
  text ".PCB_Rev" at 53.035,-16.667 h1.52
  text "REV:" at 60.439,-16.667 h1.52
  text ".PRJ_Number" at 81.89,-16.667 h1.52
  text "BOARD #:" at 95.745,-16.667 h1.52
  text "PCB VIEWED FROM BOTTOM SIDE" at 158.648,-16.667 h1.52
  text "TEXAS INSTRUMENTS" at 22.974,-27.047 h1.52
  text ".Print_Time" at 55.093,-27.047 h1.52
  text ".Print_Date" at 73.609,-27.047 h1.52
  text "GENERATED    :" at 95.694,-27.047 h1.52
  text ".plot_File_Name" at 138.189,-27.047 h1.52
  text "PLOT NAME =" at 158.648,-27.047 h1.52
M9 Title Sheet:
  lines w0.254: -12.484,26.454 -7.404,26.454 ; -12.484,86.779 -7.404,86.779 ; -12.484,147.104 -7.404,147.104 ; 51.016,-33.871 51.016,-28.791 ; 51.016,202.349 51.016,207.429 ; 114.516,-33.871 114.516,-28.791 ; 114.516,202.349 114.516,207.429 ; 160.553,-28.791 160.553,-13.297 287.109,-13.297 ; 178.016,-33.871 178.016,-28.791 ; 178.016,202.349 178.016,207.429 ; 241.516,-33.871 241.516,-28.791 ; 241.516,202.349 241.516,207.429 ; 287.109,-28.791 287.109,-13.297 ; 287.109,-20.917 363.309,-20.917 ; 287.109,-5.677 363.309,-5.677 ; 287.134,9.411 363.334,9.411 ; 305.016,-33.871 305.016,-28.791 ; 305.016,202.349 305.016,207.429 ; 325.336,-28.537 325.336,-13.297 ; 363.309,-13.297 287.109,-13.297 ; 363.309,1.943 287.109,1.943 ; 363.436,1.689 363.436,-28.791 ; 363.436,22.123 287.134,22.123 287.109,22.123 287.109,9.411 287.109,1.943 ; 363.436,26.454 368.516,26.454 ; 363.436,86.779 368.516,86.779 ; 363.436,147.104 368.516,147.104 ; 287.109,-13.297 287.109,1.943 ; 363.436,-28.791 363.436,202.349 -7.404,202.349 -7.404,-28.791 363.436,-28.791 ; -12.484,-33.871 -12.484,207.429 368.516,207.429 368.516,-33.871 -12.484,-33.871
  text "1" at 18.792,204.127 h1.78
  text "2" at 82.182,204.127 h1.78
  text "3" at 145.411,204.127 h1.78
  text "4" at 209.08,204.127 h1.78
  text "5" at 272.555,204.127 h1.78
  text "6" at 336.182,204.127 h1.78
  text "A" at -10.579,175.095 h1.78
  text "A" at 365.341,175.095 h1.78
  text "B" at -10.579,114.643 h1.78
  text "B" at 365.341,114.643 h1.78
  text "C" at -10.579,54.318 h1.78
  text "C" at 365.341,54.318 h1.78
  text "PROJECT TITLE:" at 288.125,7.048 h1.14
  text ".PRJ_Title" at 289.395,3.662 h1.78
  text "DESIGNED FOR:" at 288.125,-0.597 h1.14
  text ".PRJ_Customer" at 289.395,-4.153 h1.78
  text "D" at -10.579,-5.88 h1.78
  text "D" at 365.341,-5.88 h1.78
  text "FILE NAME:" at 288.125,-8.217 h1.14
  text ".PCB_File_Name_No_Path" at 289.395,-11.265 h1.78
  text "Texas Instruments (TI) and/or its licensors do not warrant the accuracy or completeness of this specification" at 161.9,-15.376 h1.14
  text "ENGINEER:" at 288.125,-15.583 h1.14
  text "LAYOUT BY:" at 326.352,-15.583 h1.14
  text "or any information contained therein. TI and/or its licensors do not warrant that this design will meet" at 160.757,-18.237 h1.14
  text ".PRJ_Engineer" at 289.395,-19.52 h1.78
  text ".PCB_Layout" at 327.635,-19.52 h1.78
  text "the specifications, will be suitable for your application or fit for any particular purpose, or will operate in" at 160.757,-21.099 h1.14
  text "ALTIUM DESIGNER VERSION:" at 326.352,-23.457 h1.14
  text "an implementation. TI and/or its licensors do not warrant that the design is production worthy. You should" at 160.757,-23.961 h1.14
  text "completely validate and test your design implementation to confirm the system functionality for your application." at 161.9,-26.822 h1.14
  text ".print_Scale" at 289.395,-26.843 h1.78
  text ".Application_BuildNumber" at 327.635,-26.843 h1.78
  text "1" at 18.792,-32.093 h1.78
  text "2" at 82.182,-32.093 h1.78
  text "3" at 145.411,-32.093 h1.78
  text "4" at 209.08,-32.093 h1.78
  text "5" at 272.555,-32.093 h1.78
  text "6" at 336.182,-32.093 h1.78
M10 Fab Notes:
  drawing of 189 lines, arcs and shapes, not listed
  text ".Layer_Name" at 287.25,164.5 h1.52
  text "DESIGN INFORMATION" at 314.503,161.447 h1.52
  text "MIN. TRACK WIDTH:" at 298.131,158.091 h1.52
  text "8" at 325.976,158.091 h1.52
  text "MIL" at 329.907,158.091 h1.52
  text "MIN. CLEARANCE:" at 298.131,154.938 h1.52
  text "0.2" at 324.452,154.938 h1.52
  text "mm" at 329.907,154.938 h1.52
  text "MIN. VIA PAD SIZE:" at 298.131,151.785 h1.52
  text "20" at 325.214,151.785 h1.52
  text "MIL" at 329.907,151.785 h1.52
  text "0.05mm (2MIL)" at 315.784,148.486 h1.52
  text "MINIMUM ANNULAR RING" at 289.769,148.277 h1.52
  text "EXTERNAL" at 333.768,148.277 h1.52
  text "PER" at 294.849,145.48 h1.52
  text "IPC-D-275 CLASS 2 LEVEL C" at 300.437,145.48 h1.52
  text "MIL, HOLES" at 338.238,142.928 h1.52
  text "+/-" at 328.27,142.709 h1.52
  text "+/-" at 349.961,142.709 h1.52
  text "REGISTRATION TOLERANCES:" at 289.769,142.682 h1.52
  text "METAL" at 320.243,142.682 h1.52
  text "5" at 334.879,142.683 h1.52
  text "3" at 356.037,142.683 h1.52
  text "MIL" at 358.99,142.682 h1.52
  text "HOLE SIZE TOLERANCE (UNLESS OTHERWISE SPECIFIED):" at 289.769,140.185 h1.52
  text "+/-" at 349.961,140.112 h1.52
  text "3" at 356.037,140.085 h1.52
  text "MIL" at 358.99,140.085 h1.52
  text "MATERIAL:" at 287.87,136.589 h1.52
  text "FR-4 High Tg" at 312.926,133.324 h1.52
  text "X" at 309.257,133.122 h1.52
  text "FR-408" at 298.563,133.007 h1.52
  text "OTHER" at 336.358,133.007 h1.52
  text "62 MIL (1.6mm) +/-10%" at 306.694,129.374 h1.52
  text "X" at 303.643,129.312 h1.52
  text "THICKNESS:" at 289.769,129.165 h1.52
  text "OTHER" at 339.33,129.165 h1.52
  text "TOLERANCE:" at 289.769,125.652 h1.52
  text "X" at 311.314,125.652 h1.52
  text "ANSI IPC-6012 TYPE 3 CLASS 2" at 315.836,125.652 h1.52
  text "OTHER +/-" at 315.835,121.989 h1.52
  text "BOW & TWIST:" at 289.769,118.302 h1.52
  text "X" at 311.314,118.302 h1.52
  text "ANSI IPC-6012 TYPE 3 CLASS 2" at 315.836,118.302 h1.52
  text "OTHER +/-" at 315.835,114.576 h1.52
  text "DRILLING:" at 287.87,111.258 h1.52
  text "NC_DRILL FILES" at 332.599,108.586 h1.52
  text "REFERENCE:" at 289.769,108.486 h1.52
  text "X" at 306.463,108.484 h1.52
  text "AS SHOWN" at 310.984,108.486 h1.52
  text "X" at 329.348,108.486 h1.52
  text "OTHER" at 340.168,104.873 h1.52
  text "PTH COPPER THICKNESS:" at 289.761,104.783 h1.52
  text "X" at 318.697,104.783 h1.52
  text "20-30 um" at 321.948,104.783 h1.52
  text "BOARD FINISH:" at 287.87,101.034 h1.52
  text "SILKSCREEN:" at 291.812,98.237 h1.52
  text "X" at 316.14,98.237 h1.52
  text "TOP" at 319.112,98.237 h1.52
  text "X" at 329.094,98.237 h1.52
  text "BOTTOM" at 332.091,98.237 h1.52
  text "SILKSCREEN COLOR:" at 291.812,94.295 h1.52
  text "X" at 316.115,94.295 h1.52
  text "WHITE" at 319.112,94.295 h1.52
  text "OTHER" at 332.091,94.295 h1.52
  text "X" at 319.442,90.652 h1.52
  text "BLUE" at 322.439,90.652 h1.52
  text "OTHER" at 338.136,90.652 h1.52
  text "SOLDER RESIST COLOR:" at 291.812,90.477 h1.52
  text "X" at 319.442,86.734 h1.52
  text "MATTE" at 322.439,86.734 h1.52
  text "SEMI-GLOSS" at 338.125,86.717 h1.52
  text "IMMERSION GOLD (ENIG)" at 314.819,82.345 h1.52
  text "ENEPIG" at 348.793,82.162 h1.52
  text "SURFACE FINISH:" at 287.87,82.136 h1.52
  text "X" at 310.298,82.136 h1.52
  text "IMM. TIN/SILVER OR EQUIV" at 296.24,78.649 h1.52
  text "OTHER" at 332.599,78.549 h1.52
  text "ARRAY/PANEL:" at 287.87,74.602 h1.52
  text "CUT AND TRIM PER M1 BOARD OUTLINE" at 314.819,74.393 h1.52
  text "N.C. ROUTE" at 314.819,70.94 h1.52
  text "X" at 332.295,70.94 h1.52
  text "V. SCORE" at 336.816,70.94 h1.52
  text "CERTIFICATION:" at 287.87,67.66 h1.52
  text "MATERIALS AND WORKMANSHIP FOR ALL PCBS" at 306.285,67.66 h1.52
  text "TO MEET OR EXCEED THE REQUIREMENTS OF:" at 306.285,65.271 h1.52
  text "X" at 297.078,62.003 h1.52
  text "ANSI IPC-A-600F CLASS ->" at 300.329,62.003 h1.52
  text "X" at 342.188,62.003 h1.52
  text "2" at 344.982,62.003 h1.52
  text "1" at 336.981,61.965 h1.52
  text "3" at 353.973,61.965 h1.52
  text "X" at 317.702,58.252 h1.52
  text "RoHS" at 320.953,58.252 h1.52
  text "OTHER" at 337.321,58.252 h1.52
  text "PER ORDER" at 347.407,58.252 h1.52
  text "ALL BOARDS MUST MEET OR EXCEED UL94-V0 REQUIREMENTS." at 288.569,54.345 h1.52
  text "PCB MUST BEAR THE UL94V-0 UL REGISTERED MATERIAL ID NUMBER" at 288.569,51.397 h1.52
  text "ADDITIONAL REQUIREMENTS:" at 287.87,47.094 h1.52
  text "MICROSECTION:" at 289.769,44.373 h1.52
  text "YES" at 312.775,44.373 h1.52
  text "REQUIRED" at 334.657,40.707 h1.52
  text "BARE BOARD ELEC. TEST:" at 289.769,40.634 h1.52
  text "NONE" at 322.935,40.634 h1.52
  text "X" at 331.66,40.634 h1.52
  text "PER ORDER" at 349.693,40.634 h1.52
  text "XX MIL VIAS REQUIRE NON-CONDUCTIVE FILL AND PLANARIZE" at 294.04,35.428 h1.5
  text "XX MIL VIAS REQUIRE CONDUCTIVE FILL AND PLANARIZE" at 294.243,32.787 h1.52
  text "OUTER XX MIL VIAS REQUIRE 50 OHM SINGLE-ENDED IMPEDANCE" at 294.218,28.637 h1.47
  text "LAYER 2 & 3 (INNER LAYERS) XX MIL WIDE, XX MIL SPACE / TRACES REQUIRE 100 OHM DIFFERENTIAL IMPEDANCE" at 294.015,22.65 h1.52
M11 Gerber Information:
  lines w0.254: -7.417,-23.626 160.223,-23.626 ; -7.417,-18.462 160.274,-18.462 ; -7.417,-13.297 -7.417,-28.791 94.31,-28.791 160.274,-28.791 160.274,-13.297 -7.404,-13.297 -7.404,-28.791 32.614,-28.791 ; 55.194,-28.791 55.194,-13.297 ; 87.376,-18.462 87.376,-13.297 ; 108.712,-18.462 108.712,-13.297 ; 124.511,-28.956 124.511,-23.804
  text "ALL ARTWORK VIEWED FROM TOP SIDE" at -5.804,-16.654 h1.52
  text "BOARD #:" at 57.099,-16.654 h1.52
  text ".PRJ_Number" at 70.955,-16.654 h1.52
  text "REV:" at 92.405,-16.654 h1.52
  text ".PCB_Rev" at 99.809,-16.654 h1.52
  text "SVN REV:" at 113.69,-16.654 h1.52
  text ".VersionControl_RevNumber" at 126.543,-16.654 h1.52
  text "LAYER NAME =" at -5.804,-21.806 h1.52
  text "PLOT NAME =" at -5.804,-27.034 h1.52
  text ".plot_File_Name" at 14.656,-27.034 h1.52
  text "GENERATED    :" at 57.15,-27.034 h1.52
  text ".Print_Date" at 79.235,-27.034 h1.52
  text ".Print_Time" at 97.752,-27.034 h1.52
  text "TEXAS INSTRUMENTS" at 129.87,-27.034 h1.52
M12 Stackup:
  drawing of 295 lines, arcs and shapes, not listed
  text ".Layer_Name" at 95.25,78 h1.52
  text "Layer" at 96.715,74.48 h1.52
  text "Name" at 107.126,74.48 h1.52
  text "Material" at 130.996,74.48 h1.52
  text "Thickness" at 152.834,74.48 h1.52
  text "Constant" at 169.34,74.48 h1.52
  text "Board Layer Stack" at 183.814,74.48 h1.52
  text "1" at 96.715,71.432 h1.52
  text "Top Overlay" at 107.126,71.432 h1.52
  text "2" at 96.715,68.384 h1.52
  text "Top Solder" at 107.126,68.384 h1.52
  text "Solder Resist" at 130.996,68.384 h1.52
  text "0.40mil" at 152.834,68.384 h1.52
  text "3.5" at 169.34,68.384 h1.52
  text "3" at 96.715,65.336 h1.52
  text "Top Layer" at 107.126,65.336 h1.52
  text "Copper" at 130.996,65.336 h1.52
  text "2.74mil" at 152.834,65.336 h1.52
  text "4" at 96.715,62.288 h1.52
  text "Dielectric 1" at 107.126,62.288 h1.52
  text "FR-4" at 130.996,62.288 h1.52
  text "8.00mil" at 152.834,62.288 h1.52
  text "4.2" at 169.34,62.288 h1.52
  text "5" at 96.715,59.24 h1.52
  text "Signal Layer 1" at 107.126,59.24 h1.52
  text "Copper" at 130.996,59.24 h1.52
  text "1.40mil" at 152.834,59.24 h1.52
  text "6" at 96.715,56.192 h1.52
  text "Dielectric 2" at 107.126,56.192 h1.52
  text "FR-4" at 130.996,56.192 h1.52
  text "37.42mil" at 152.834,56.192 h1.52
  text "4.2" at 169.34,56.192 h1.52
  text "7" at 96.715,53.144 h1.52
  text "Signal Layer 2" at 107.126,53.144 h1.52
  text "Copper" at 130.996,53.144 h1.52
  text "1.40mil" at 152.834,53.144 h1.52
  text "8" at 96.715,50.096 h1.52
  text "Dielectric 3" at 107.126,50.096 h1.52
  text "FR-4" at 130.996,50.096 h1.52
  text "8.00mil" at 152.834,50.096 h1.52
  text "4.2" at 169.34,50.096 h1.52
  text "9" at 96.715,47.048 h1.52
  text "Bottom Layer" at 107.126,47.048 h1.52
  text "Copper" at 130.996,47.048 h1.52
  text "2.74mil" at 152.834,47.048 h1.52
  text "10" at 96.715,44 h1.52
  text "Bottom Solder" at 107.126,44 h1.52
  text "Solder Resist" at 130.996,44 h1.52
  text "0.40mil" at 152.834,44 h1.52
  text "3.5" at 169.34,44 h1.52
  text "11" at 96.715,40.952 h1.52
  text "Bottom Overlay" at 107.126,40.952 h1.52
M13 Component Bodies Top:
  text ".Layer_Name" at 14.656,-21.806 h1.52
M14 Component Bodies Bottom:
  text ".Layer_Name" at 14.656,-21.806 h1.52
M15 Courtyards Top:
  text ".Layer_Name" at 14.656,-21.806 h1.52
M16 Courtyards Bottom:
  text ".Layer_Name" at 14.656,-21.806 h1.52
Drill Drawing:
  lines w0.254: 96.425,4.257 97.126,4.608 97.828,4.257 97.477,4.959 97.828,5.661 97.126,5.31 96.425,5.661 96.776,4.959 96.425,4.257 ; 96.425,8.819 97.828,8.819 97.126,7.415 96.425,8.819 ; 96.425,10.924 96.776,10.924 96.776,10.573 97.477,10.573 97.477,10.924 97.828,10.924 97.828,11.625 97.477,11.625 97.477,11.976 96.776,11.976 96.776,11.625 96.425,11.625 96.425,10.924 ; 96.425,13.731 97.828,13.731 97.828,15.134 96.425,15.134 96.425,13.731 ; 96.425,17.59 97.126,16.888 97.828,17.59 97.126,18.292 96.425,17.59 ; 96.425,20.046 97.828,20.046 97.828,21.45 96.425,21.45 96.425,20.046 ; 96.425,23.555 96.776,23.555 97.126,23.204 97.477,23.555 97.828,23.555 97.477,23.906 97.828,24.256 97.477,24.256 97.126,24.607 96.776,24.256 96.425,24.256 96.776,23.906 96.425,23.555 ; 96.705,20.327 97.547,20.327 97.547,21.169 96.705,21.169 96.705,20.327
  lines w0.305: 95.152,3.31 163.792,3.31 ; 95.152,25.414 163.792,25.414 ; 103.734,0.152 103.734,28.572 ; 112.167,0.152 112.167,28.572 ; 128.336,0.152 128.336,28.572 ; 134.918,0.152 134.918,28.572 ; 144.447,0.152 144.447,28.572 ; 95.152,0.152 163.792,0.152 163.792,28.572 95.152,28.572 95.152,0.152
  text "Symbol" at 97.047,26.362 h1.83
  text "Quantity" at 104.681,26.362 h1.83
  text "Finished Hole Size" at 113.114,26.362 h1.83
  text "Plated" at 129.283,26.362 h1.83
  text "Hole Type" at 135.865,26.362 h1.83
  text "Drill Layer Pair" at 145.394,26.362 h1.83
  text "2" at 104.681,23.204 h1.52
  text "40.00mil (1.016mm)" at 113.114,23.204 h1.52
  text "NPTH" at 129.283,23.204 h1.52
  text "Round" at 135.865,23.204 h1.52
  text "Top Layer - Bottom Layer" at 145.394,23.204 h1.52
  text "10" at 104.681,20.046 h1.52
  text "7.87mil (0.200mm)" at 113.114,20.046 h1.52
  text "PTH" at 129.283,20.046 h1.52
  text "Round" at 135.865,20.046 h1.52
  text "Top Layer - Bottom Layer" at 145.394,20.046 h1.52
  text "495" at 104.681,16.888 h1.52
  text "10.00mil (0.254mm)" at 113.114,16.888 h1.52
  text "PTH" at 129.283,16.888 h1.52
  text "Round" at 135.865,16.888 h1.52
  text "Top Layer - Bottom Layer" at 145.394,16.888 h1.52
  text "22" at 104.681,13.731 h1.52
  text "40.00mil (1.016mm)" at 113.114,13.731 h1.52
  text "PTH" at 129.283,13.731 h1.52
  text "Round" at 135.865,13.731 h1.52
  text "Top Layer - Bottom Layer" at 145.394,13.731 h1.52
  text "8" at 104.681,10.573 h1.52
  text "70.00mil (1.778mm)" at 113.114,10.573 h1.52
  text "PTH" at 129.283,10.573 h1.52
  text "Round" at 135.865,10.573 h1.52
  text "Top Layer - Bottom Layer" at 145.394,10.573 h1.52
  text "6" at 104.681,7.415 h1.52
  text "127.95mil (3.250mm)" at 113.114,7.415 h1.52
  text "PTH" at 129.283,7.415 h1.52
  text "Round" at 135.865,7.415 h1.52
  text "Top Layer - Bottom Layer" at 145.394,7.415 h1.52
  text "2" at 104.681,4.257 h1.52
  text "144.00mil (3.658mm)" at 113.114,4.257 h1.52
  text "PTH" at 129.283,4.257 h1.52
  text "Round" at 135.865,4.257 h1.52
  text "Top Layer - Bottom Layer" at 145.394,4.257 h1.52
  text "545 Total" at 104.681,1.1 h1.52
  text ".Layer_Name" at 14.656,-21.806 h1.52
Mechanical 17:
  lines w0.25: -5,60 76,60 ; 8,60 10,60 ; 48.75,10 85,25 ; 48.75,40 85,25 ; 48.75,80 85,95 ; 48.75,110 85,95 ; 55,14 85,14 ; 55,25 85,25 ; 55,36 85,36 ; 55,84 85,84 ; 55,95 85,95 ; 55,106 85,106 ; 9,59 9,61 9,59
